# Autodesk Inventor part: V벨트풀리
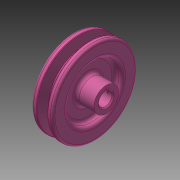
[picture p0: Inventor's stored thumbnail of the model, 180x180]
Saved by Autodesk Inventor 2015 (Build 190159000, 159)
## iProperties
Created: 2015-11
Part Number: V벨트풀리
Material: 강철, 탄소
Document SubType Name: Modeling
Designer: mduedu
Density: 1 g/cm^3
Appearance: 분홍색
Author: mduedu
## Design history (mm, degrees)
sketch "스케치1"
  geometry: L1 (-9.5, 0)-(9.5, 0); L2 (0, 0)-(0, 37.7); L3 (-4.825, 37.7)-(-9.5, 37.7); L4 (-9.5, 37.7)-(-9.5, 0); L5 (0, 28.7)-(-2.074, 28.7); L6 (-2.074, 28.7)-(-4.825, 37.7); L7 (4.825, 37.7)-(9.5, 37.7); L8 (9.5, 37.7)-(9.5, 0); L9 (0, 28.7)-(2.074, 28.7); L10 (2.074, 28.7)-(4.825, 37.7); L11 (-9.5, 35)-(9.5, 35); 3 further points
  constraints: 22 end point, 7 point on line, 4 perpendicular, 3 symmetric about line, 1 coincident, 1 horizontal, 1 horizontal alignment, 1 midpoint, 1 vertical
  dimensions: "d0" = 19 distance of L1.start L1.end; "d2" = 75.4 diameter of L2.end L1 (derived); "d3" = 34 deg angle of L10 L6; "d4" = 6.3 distance between parallel lines of L11 L9; "d5" = 2.7 distance between parallel lines of L7 L11; "d6" = 8 distance of point (4, 35) point (-4, 35); "d7" = 70 diameter of L11 L1
revolve "회전1" sketch "스케치1" stored, may be unused: angle "d8" = 90 deg
sketch "스케치2"
  geometry: C1 r 24 at (0, 0); C2 r 11 at (0, 0); 1 further point
  constraints: 2 centre point, 2 coincident
  dimensions: "d9" = 48 diameter of C1; "d10" = 22 diameter of C2
extrude "돌출1" cut sketch "스케치2" distance "d11" = 6; taper "d12" = 0 deg
extrude "돌출3" join sketch "스케치2" distance "d37" = 10; taper "d38" = 0 deg
fillet "모깎기1" dims "d13" = 3
fillet "모깎기2" dims "d14" = 3
fillet "모깎기3" dims "d15" = 1, "d16" = 0.5, "d17" = 2
hole "구멍1" diameter "d20" = 12; stored, may be unused: countersink angle "d24" = 90 deg, drill point angle "d26" = 118 deg; dims "d21" = 6, "d22" = 4, "d23" = 2, "d25" = 8, "d39" = 10, "d40" = 10
sketch "스케치3"
  geometry: L1 (-2, 0)-(2, 0); L2 (2, 0)-(2, 7.8); L3 (2, 7.8)-(-2, 7.8); L4 (-2, 7.8)-(-2, 0); 2 further points
  constraints: 8 end point, 2 parallel, 1 coincident, 1 horizontal, 1 midpoint, 1 perpendicular
  dimensions: "d27" = 4 distance of L2.end L3.end; "d29" = 7.8 distance of L3.end L1.start
extrude "돌출2" cut sketch "스케치3" stored distance "d30" = 6; taper "d31" = 0 deg
chamfer "모따기1" distance "d32" = 1; stored, may be unused: second distance "d33" = 2, angle "d34" = 45 deg
node "작업 평면1"
sketch "스케치4"
  geometry: L1 (-19, 11)-(-19, -11) reference; 2 further points
  constraints: 1 horizontal alignment
  dimensions: "d41" = 25 distance from line of point (6, 0) L1
hole "구멍2" sketch "스케치4" at (6, 0) diameter "d42" = 2.459; stored, may be unused: countersink angle "d46" = 90 deg, drill point angle "d48" = 118 deg; dims "d43" = 6, "d44" = 4, "d45" = 2, "d47" = 8
chamfer "모따기2" distance "d49" = 1; stored, may be unused: second distance "d50" = 2, angle "d51" = 45 deg
node "솔리드1"
mirror "대칭1"
